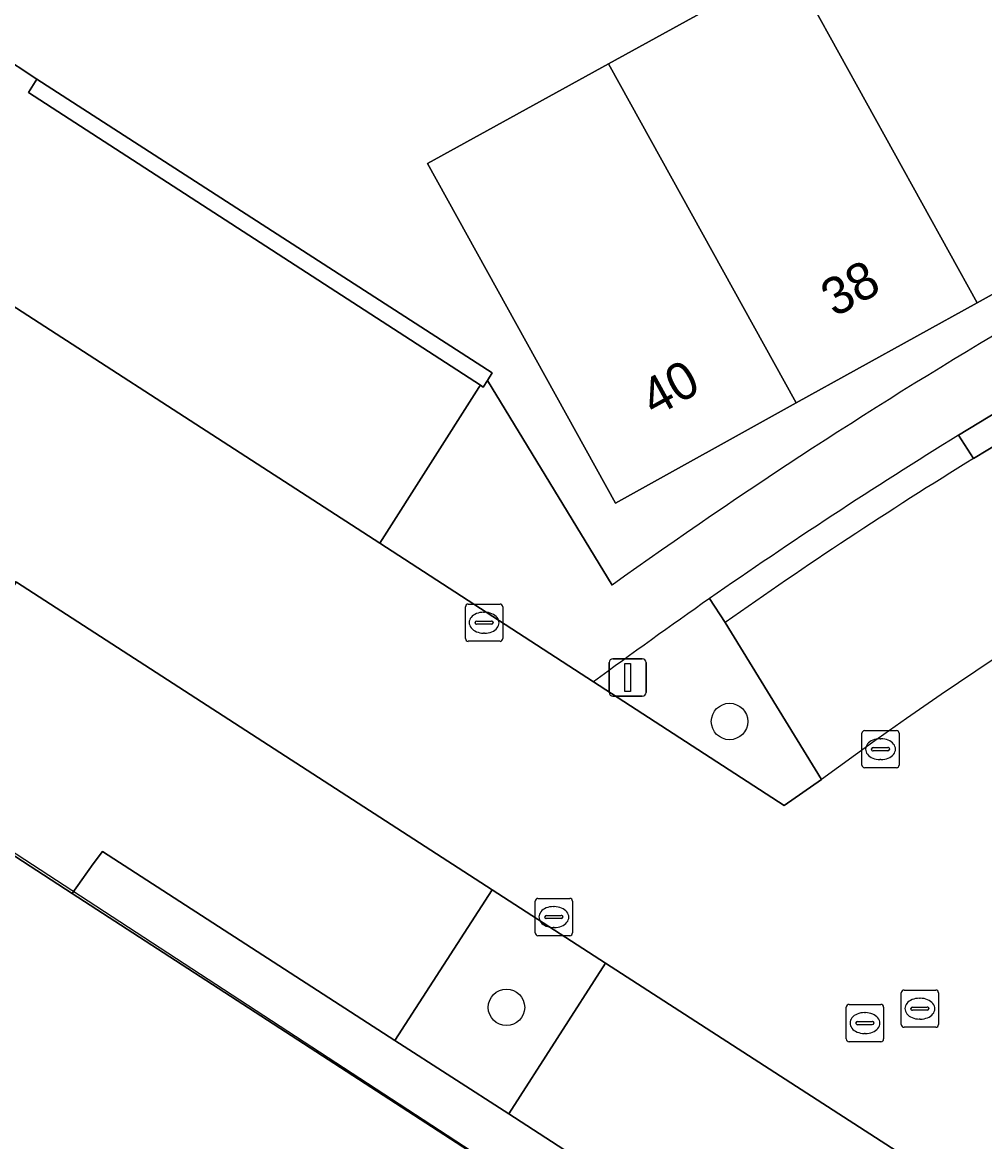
# Model space of a CAD drawing. Extents: x 160157 to 160921, y 381516 to 382045.
# Drawn here: x 160390.97 to 160416.8, y 381613.78 to 381643.81 of the extents above; entities that cross this region are included whole.
import ezdxf

# ---------------------------------------------------------------- set-up
doc = ezdxf.new("R2010")
doc.units = 0
for name, color, linetype in [('IMGEO_Boom', 7, 'Continuous'), ('IMGEO_Erf', 7, 'Continuous'), ('IMGEO_Groenvoorziening', 7, 'Continuous'), ('IMGEO_Haag', 7, 'Continuous'), ('IMGEO_Kolk', 7, 'Continuous'), ('IMGEO_Lichtmast', 7, 'Continuous'), ('IMGEO_Muur', 7, 'Continuous'), ('IMGEO_Pand', 7, 'Continuous'), ('IMGEO_Pand_nummerreeks', 7, 'Continuous'), ('IMGEO_Parkeervlak_open', 7, 'Continuous'), ('IMGEO_Rijbaan_lokaal_open', 7, 'Continuous'), ('IMGEO_Rioolput', 7, 'Continuous'), ('IMGEO_Voetpad_open', 7, 'Continuous')]:
    doc.layers.add(name, color=color, linetype=linetype)

msp = doc.modelspace()

# ---------------------------------------------------------------- linework, layer by layer
at = {"layer": 'IMGEO_Boom'}
for centre in [(160409.95, 381625.053), (160403.963, 381617.381)]:
    msp.add_circle(centre, 0.489, dxfattribs=at)
at = {"layer": 'IMGEO_Erf'}
msp.add_lwpolyline([(160406.702, 381642.702), (160411.96, 381645.599), (160412.556, 381644.569), (160416.994, 381647.031), (160421.602, 381649.587), (160421.022, 381650.637), (160426.124, 381653.458), (160431.165, 381644.355), (160426.309, 381641.667), (160421.453, 381638.979), (160416.597, 381636.291), (160411.741, 381633.603), (160406.885, 381630.915), (160401.847, 381640.026)], close=True, dxfattribs=at)
for points in [[(160378.993, 381629.081), (160390.212, 381643.048), (160390.324, 381642.974), (160391.362, 381642.286), (160403.578, 381634.406), (160403.453, 381634.202), (160406.797, 381628.714)], [(160319.436, 381635.145), (160331.317, 381627.79), (160361.156, 381608.556), (160362.318, 381609.828), (160405.188, 381582.297), (160414.171, 381576.508), (160427.676, 381597.123), (160427.729, 381597.121), (160427.898, 381597.365), (160424.706, 381599.434), (160411.1, 381608.252), (160410.955, 381608.346), (160409.818, 381609.084), (160392.312, 381620.441), (160387.378, 381623.641), (160380.613, 381628.03), (160378.993, 381629.081)]]:
    msp.add_lwpolyline(points, dxfattribs=at)
msp.add_arc((160492.712, 381508.556), 147.714, 115.46429, 125.56554, dxfattribs=at)
at = {"layer": 'IMGEO_Groenvoorziening'}
for points in [[(160391.362, 381642.286), (160391.135, 381641.935), (160403.263, 381634.078), (160403.342, 381634.026), (160403.453, 381634.202), (160403.578, 381634.406)], [(160400.97, 381616.489), (160393.122, 381621.564), (160392.872, 381621.233), (160392.567, 381620.809), (160392.312, 381620.441), (160409.818, 381609.084), (160410.056, 381609.447), (160410.307, 381609.829), (160410.593, 381610.266), (160404.025, 381614.525)], [(160403.579, 381620.534), (160400.97, 381616.489), (160404.025, 381614.525), (160406.623, 381618.572)]]:
    msp.add_lwpolyline(points, close=True, dxfattribs=at)
for points in [[(160416.501, 381632.114), (160416.095, 381632.737)], [(160409.834, 381627.714), (160409.416, 381628.353)], [(160409.416, 381628.353), (160409.834, 381627.714)], [(160406.303, 381626.118), (160411.413, 381622.801), (160412.421, 381623.498), (160409.834, 381627.714)]]:
    msp.add_lwpolyline(points, dxfattribs=at)
for centre, radius, start, end in [((160490.755, 381511.713), 142.2, 121.67057, 124.89007), ((160485.152, 381520.84), 130.747, 121.67297, 125.17402), ((160490.828, 381511.673), 142.275, 124.90505, 126.44839)]:
    msp.add_arc(centre, radius, start, end, dxfattribs=at)
at = {"layer": 'IMGEO_Haag'}
for points in [[(160391.362, 381642.286), (160391.135, 381641.935), (160403.263, 381634.078), (160403.342, 381634.026), (160403.453, 381634.202), (160403.578, 381634.406)], [(160392.872, 381621.233), (160392.567, 381620.809), (160392.312, 381620.441), (160409.818, 381609.084), (160410.056, 381609.447), (160410.307, 381609.829), (160410.593, 381610.266), (160404.025, 381614.525), (160400.97, 381616.489), (160393.122, 381621.564)]]:
    msp.add_lwpolyline(points, close=True, dxfattribs=at)
for points in [[(160416.501, 381632.114), (160416.095, 381632.737)], [(160409.416, 381628.353), (160409.834, 381627.714)]]:
    msp.add_lwpolyline(points, dxfattribs=at)
for centre, radius, start, end in [((160490.755, 381511.713), 142.2, 121.67057, 124.89007), ((160485.152, 381520.84), 130.747, 121.67297, 125.17402)]:
    msp.add_arc(centre, radius, start, end, dxfattribs=at)
at = {"layer": 'IMGEO_Kolk'}
for p, q in [((160402.863, 381627.279), (160402.863, 381628.131)), ((160402.938, 381628.205), (160403.79, 381628.205)), ((160403.864, 381628.131), (160403.864, 381627.279)), ((160403.165, 381627.748), (160403.563, 381627.748)), ((160403.351, 381627.985), (160403.376, 381627.985)), ((160403.122, 381627.699), (160403.122, 381627.711)), ((160403.56, 381627.662), (160403.162, 381627.662)), ((160403.606, 381627.711), (160403.606, 381627.699)), ((160403.79, 381627.205), (160402.938, 381627.205)), ((160403.374, 381627.425), (160403.349, 381627.425)), ((160413.501, 381623.885), (160413.501, 381624.737)), ((160413.576, 381624.811), (160414.428, 381624.811)), ((160414.502, 381624.737), (160414.502, 381623.885)), ((160413.989, 381624.591), (160414.014, 381624.591)), ((160413.76, 381624.305), (160413.76, 381624.317)), ((160414.198, 381624.268), (160413.8, 381624.268)), ((160413.803, 381624.354), (160414.201, 381624.354)), ((160414.244, 381624.317), (160414.244, 381624.305)), ((160414.012, 381624.031), (160413.987, 381624.031)), ((160414.428, 381623.811), (160413.576, 381623.811)), ((160404.734, 381619.38), (160404.734, 381620.232)), ((160404.809, 381620.306), (160405.661, 381620.306)), ((160405.735, 381620.232), (160405.735, 381619.38)), ((160405.222, 381620.086), (160405.247, 381620.086)), ((160404.993, 381619.8), (160404.993, 381619.812)), ((160405.431, 381619.763), (160405.033, 381619.763)), ((160405.036, 381619.849), (160405.434, 381619.849)), ((160405.477, 381619.812), (160405.477, 381619.8)), ((160405.245, 381619.526), (160405.22, 381619.526)), ((160405.661, 381619.306), (160404.809, 381619.306))]:
    msp.add_line(p, q, dxfattribs=at)
for points in [[(160402.863, 381627.279), (160402.863, 381628.131)], [(160402.938, 381628.205), (160403.79, 381628.205)], [(160403.864, 381628.131), (160403.864, 381627.279)], [(160403.79, 381627.205), (160402.938, 381627.205)], [(160413.501, 381623.885), (160413.501, 381624.737)], [(160413.576, 381624.811), (160414.428, 381624.811)], [(160414.502, 381624.737), (160414.502, 381623.885)], [(160414.428, 381623.811), (160413.576, 381623.811)], [(160404.734, 381619.38), (160404.734, 381620.232)], [(160404.809, 381620.306), (160405.661, 381620.306)], [(160405.735, 381620.232), (160405.735, 381619.38)], [(160405.661, 381619.306), (160404.809, 381619.306)]]:
    msp.add_lwpolyline(points, dxfattribs=at)
for centre, radius, start, end in [((160402.94, 381628.129), 0.0765, 91.552, 178.448), ((160402.94, 381628.129), 0.0765, 91.552, 178.448), ((160403.788, 381628.129), 0.0765, 1.552, 88.448), ((160403.788, 381628.129), 0.0765, 1.552, 88.448), ((160403.162, 381627.708), 0.0403, 85.8775, 175.7526), ((160403.567, 381627.71), 0.0386, 1.7309, 96.639), ((160403.159, 381627.698), 0.0366, 178.938, 274.7102), ((160403.563, 381627.705), 0.043, 264.8664, 352.4533), ((160402.94, 381627.281), 0.0765, 181.552, 268.448), ((160402.94, 381627.281), 0.0765, 181.552, 268.448), ((160403.788, 381627.281), 0.0765, 271.552, 358.448), ((160403.788, 381627.281), 0.0765, 271.552, 358.448), ((160413.578, 381624.735), 0.0765, 91.552, 178.448), ((160413.578, 381624.735), 0.0765, 91.552, 178.448), ((160414.426, 381624.735), 0.0765, 1.552, 88.448), ((160414.426, 381624.735), 0.0765, 1.552, 88.448), ((160413.8, 381624.314), 0.0403, 85.8775, 175.7526), ((160413.797, 381624.304), 0.0366, 178.938, 274.7102), ((160414.201, 381624.311), 0.043, 264.8664, 352.4533), ((160414.205, 381624.316), 0.0386, 1.7309, 96.639), ((160413.578, 381623.887), 0.0765, 181.552, 268.448), ((160413.578, 381623.887), 0.0765, 181.552, 268.448), ((160414.426, 381623.887), 0.0765, 271.552, 358.448), ((160414.426, 381623.887), 0.0765, 271.552, 358.448), ((160404.811, 381620.23), 0.0765, 91.552, 178.448), ((160404.811, 381620.23), 0.0765, 91.552, 178.448), ((160405.659, 381620.23), 0.0765, 1.552, 88.448), ((160405.659, 381620.23), 0.0765, 1.552, 88.448), ((160405.033, 381619.809), 0.0403, 85.8775, 175.7526), ((160405.03, 381619.799), 0.0366, 178.938, 274.7102), ((160405.434, 381619.806), 0.043, 264.8664, 352.4533), ((160405.438, 381619.811), 0.0386, 1.7309, 96.639), ((160404.811, 381619.382), 0.0765, 181.552, 268.448), ((160404.811, 381619.382), 0.0765, 181.552, 268.448), ((160405.659, 381619.382), 0.0765, 271.552, 358.448), ((160405.659, 381619.382), 0.0765, 271.552, 358.448)]:
    msp.add_arc(centre, radius, start, end, dxfattribs=at)
for centre, major_axis, ratio, start_param, end_param in [((160403.35, 381627.705), (-0.387, 0.002), 0.722429, 4.712389, 7.853982), ((160403.375, 381627.705), (-0.39, 0.002), 0.717154, 1.570796, 4.712389), ((160413.988, 381624.311), (-0.387, 0.002), 0.722429, 4.712389, 7.853982), ((160414.013, 381624.311), (-0.39, 0.002), 0.717154, 1.570796, 4.712389), ((160405.221, 381619.806), (-0.387, 0.002), 0.722429, 4.712389, 7.853982), ((160405.246, 381619.806), (-0.39, 0.002), 0.717154, 1.570796, 4.712389)]:
    msp.add_ellipse(centre, major_axis=major_axis, ratio=ratio, start_param=start_param, end_param=end_param, dxfattribs=at)
at = {"layer": 'IMGEO_Lichtmast'}
for p, q in [((160406.719, 381625.833), (160406.719, 381626.633)), ((160406.719, 381626.633), (160406.719, 381625.833)), ((160406.819, 381626.733), (160407.609, 381626.733)), ((160407.609, 381626.733), (160406.819, 381626.733)), ((160407.709, 381626.633), (160407.709, 381625.833)), ((160407.709, 381625.833), (160407.709, 381626.633)), ((160407.609, 381625.733), (160406.819, 381625.733)), ((160406.819, 381625.733), (160407.609, 381625.733))]:
    msp.add_line(p, q, dxfattribs=at)
msp.add_lwpolyline([(160407.139, 381626.608), (160407.289, 381626.608), (160407.289, 381625.858), (160407.139, 381625.858), (160407.139, 381626.608)], dxfattribs=at)
for centre, start, end in [((160406.819, 381626.633), 90, 180), ((160406.819, 381626.633), 90, 180), ((160407.609, 381626.633), 0, 90), ((160407.609, 381626.633), 360, 90), ((160406.819, 381625.833), 180, 270), ((160406.819, 381625.833), 180, 270), ((160407.609, 381625.833), 270, 0), ((160407.609, 381625.833), 270, 0)]:
    msp.add_arc(centre, 0.1, start, end, dxfattribs=at)
at = {"layer": 'IMGEO_Muur'}
msp.add_lwpolyline([(160410.955, 381608.346), (160385.879, 381624.702)], dxfattribs=at)
at = {"layer": 'IMGEO_Pand'}
for points in [[(160416.994, 381647.031), (160412.556, 381644.569), (160412.141, 381644.339), (160416.597, 381636.291), (160421.453, 381638.979)], [(160412.141, 381644.339), (160412.556, 381644.569), (160411.96, 381645.599), (160406.702, 381642.702), (160411.741, 381633.603), (160416.597, 381636.291)], [(160406.702, 381642.702), (160401.847, 381640.026), (160406.885, 381630.915), (160411.741, 381633.603)]]:
    msp.add_lwpolyline(points, close=True, dxfattribs=at)
at = {"layer": 'IMGEO_Parkeervlak_open'}
for points in [[(160403.222, 381634.014), (160403.263, 381634.078), (160391.135, 381641.935), (160391.362, 381642.286), (160390.324, 381642.974), (160387.357, 381638.374), (160400.563, 381629.843)], [(160390.812, 381628.788), (160390.808, 381628.79), (160388.223, 381624.732), (160388.119, 381624.799), (160387.901, 381624.465), (160387.646, 381624.063), (160387.378, 381623.641), (160392.312, 381620.441), (160392.567, 381620.809), (160392.872, 381621.233), (160393.122, 381621.564), (160400.97, 381616.489), (160403.579, 381620.534)], [(160406.623, 381618.572), (160404.025, 381614.525), (160410.593, 381610.266), (160411.859, 381609.445), (160425.31, 381600.723), (160427.931, 381604.811)]]:
    msp.add_lwpolyline(points, close=True, dxfattribs=at)
for points in [[(160418.418, 381633.276), (160416.501, 381632.114)], [(160409.834, 381627.714), (160412.421, 381623.498)]]:
    msp.add_lwpolyline(points, dxfattribs=at)
for centre, radius, start, end in [((160476.35, 381536.857), 107.674, 116.85616, 126.42198), ((160485.152, 381520.84), 130.747, 121.67297, 125.17402)]:
    msp.add_arc(centre, radius, start, end, dxfattribs=at)
at = {"layer": 'IMGEO_Rijbaan_lokaal_open'}
msp.add_lwpolyline([(160412.421, 381623.498), (160411.413, 381622.801), (160406.303, 381626.118), (160400.563, 381629.843), (160387.357, 381638.374), (160384.01, 381633.185), (160390.141, 381629.222), (160390.15, 381629.216), (160390.808, 381628.79), (160390.812, 381628.788), (160403.579, 381620.534), (160406.623, 381618.572), (160427.931, 381604.811)], dxfattribs=at)
msp.add_arc((160476.35, 381536.857), 107.674, 116.85616, 126.42198, dxfattribs=at)
at = {"layer": 'IMGEO_Rioolput'}
for p, q in [((160414.632, 381617.847), (160415.484, 381617.847)), ((160414.557, 381616.921), (160414.557, 381617.773)), ((160415.045, 381617.627), (160415.07, 381617.627)), ((160415.558, 381617.773), (160415.558, 381616.921)), ((160413.083, 381616.535), (160413.083, 381617.387)), ((160413.158, 381617.461), (160414.01, 381617.461)), ((160413.571, 381617.241), (160413.596, 381617.241)), ((160414.084, 381617.387), (160414.084, 381616.535)), ((160414.816, 381617.341), (160414.816, 381617.353)), ((160415.254, 381617.304), (160414.856, 381617.304)), ((160414.859, 381617.39), (160415.257, 381617.39)), ((160415.3, 381617.353), (160415.3, 381617.341)), ((160413.342, 381616.955), (160413.342, 381616.967)), ((160413.385, 381617.004), (160413.783, 381617.004)), ((160413.826, 381616.967), (160413.826, 381616.955)), ((160415.068, 381617.067), (160415.043, 381617.067)), ((160413.78, 381616.918), (160413.382, 381616.918)), ((160413.594, 381616.681), (160413.569, 381616.681)), ((160415.484, 381616.847), (160414.632, 381616.847)), ((160414.01, 381616.461), (160413.158, 381616.461))]:
    msp.add_line(p, q, dxfattribs=at)
for points in [[(160414.632, 381617.847), (160415.484, 381617.847)], [(160414.557, 381616.921), (160414.557, 381617.773)], [(160415.558, 381617.773), (160415.558, 381616.921)], [(160413.083, 381616.535), (160413.083, 381617.387)], [(160413.158, 381617.461), (160414.01, 381617.461)], [(160414.084, 381617.387), (160414.084, 381616.535)], [(160415.484, 381616.847), (160414.632, 381616.847)], [(160414.01, 381616.461), (160413.158, 381616.461)]]:
    msp.add_lwpolyline(points, dxfattribs=at)
for centre, radius, start, end in [((160414.634, 381617.771), 0.0765, 91.552, 178.448), ((160414.634, 381617.771), 0.0765, 91.552, 178.448), ((160415.482, 381617.771), 0.0765, 1.552, 88.448), ((160415.482, 381617.771), 0.0765, 1.552, 88.448), ((160413.16, 381617.385), 0.0765, 91.552, 178.448), ((160413.16, 381617.385), 0.0765, 91.552, 178.448), ((160414.008, 381617.385), 0.0765, 1.552, 88.448), ((160414.008, 381617.385), 0.0765, 1.552, 88.448), ((160414.856, 381617.35), 0.0403, 85.8775, 175.7526), ((160414.853, 381617.34), 0.0366, 178.938, 274.7102), ((160415.257, 381617.347), 0.043, 264.8664, 352.4533), ((160415.261, 381617.352), 0.0386, 1.7309, 96.639), ((160413.382, 381616.964), 0.0403, 85.8775, 175.7526), ((160413.379, 381616.954), 0.0366, 178.938, 274.7102), ((160413.783, 381616.961), 0.043, 264.8664, 352.4533), ((160413.787, 381616.966), 0.0386, 1.7309, 96.639), ((160414.634, 381616.923), 0.0765, 181.552, 268.448), ((160414.634, 381616.923), 0.0765, 181.552, 268.448), ((160415.482, 381616.923), 0.0765, 271.552, 358.448), ((160415.482, 381616.923), 0.0765, 271.552, 358.448), ((160413.16, 381616.537), 0.0765, 181.552, 268.448), ((160413.16, 381616.537), 0.0765, 181.552, 268.448), ((160414.008, 381616.537), 0.0765, 271.552, 358.448), ((160414.008, 381616.537), 0.0765, 271.552, 358.448)]:
    msp.add_arc(centre, radius, start, end, dxfattribs=at)
for centre, major_axis, ratio, start_param, end_param in [((160415.044, 381617.347), (-0.387, 0.002), 0.722429, 4.712389, 7.853982), ((160415.069, 381617.347), (-0.39, 0.002), 0.717154, 1.570796, 4.712389), ((160413.57, 381616.961), (-0.387, 0.002), 0.722429, 4.712389, 7.853982), ((160413.595, 381616.961), (-0.39, 0.002), 0.717154, 1.570796, 4.712389)]:
    msp.add_ellipse(centre, major_axis=major_axis, ratio=ratio, start_param=start_param, end_param=end_param, dxfattribs=at)
at = {"layer": 'IMGEO_Voetpad_open'}
for points in [[(160406.797, 381628.714), (160403.453, 381634.202), (160403.342, 381634.026), (160403.263, 381634.078), (160403.222, 381634.014), (160400.563, 381629.843), (160406.303, 381626.118)], [(160416.095, 381632.737), (160418.023, 381633.905)]]:
    msp.add_lwpolyline(points, dxfattribs=at)
msp.add_lwpolyline([(160418.418, 381633.276), (160418.023, 381633.905), (160416.095, 381632.737), (160416.501, 381632.114)], close=True, dxfattribs=at)
for centre, radius, start, end in [((160492.712, 381508.556), 147.714, 115.46429, 125.56554), ((160490.755, 381511.713), 142.2, 121.67057, 124.89007), ((160490.828, 381511.673), 142.275, 124.90505, 126.44839)]:
    msp.add_arc(centre, radius, start, end, dxfattribs=at)

# ---------------------------------------------------------------- texts
at = {"layer": 'IMGEO_Pand_nummerreeks'}
for s, p in [('38', (160412.772, 381635.888)), ('40', (160407.931, 381633.209))]:
    msp.add_text(s, height=1, rotation=28.9687, dxfattribs=at).set_placement(p)

doc.saveas('drawing.dxf')
